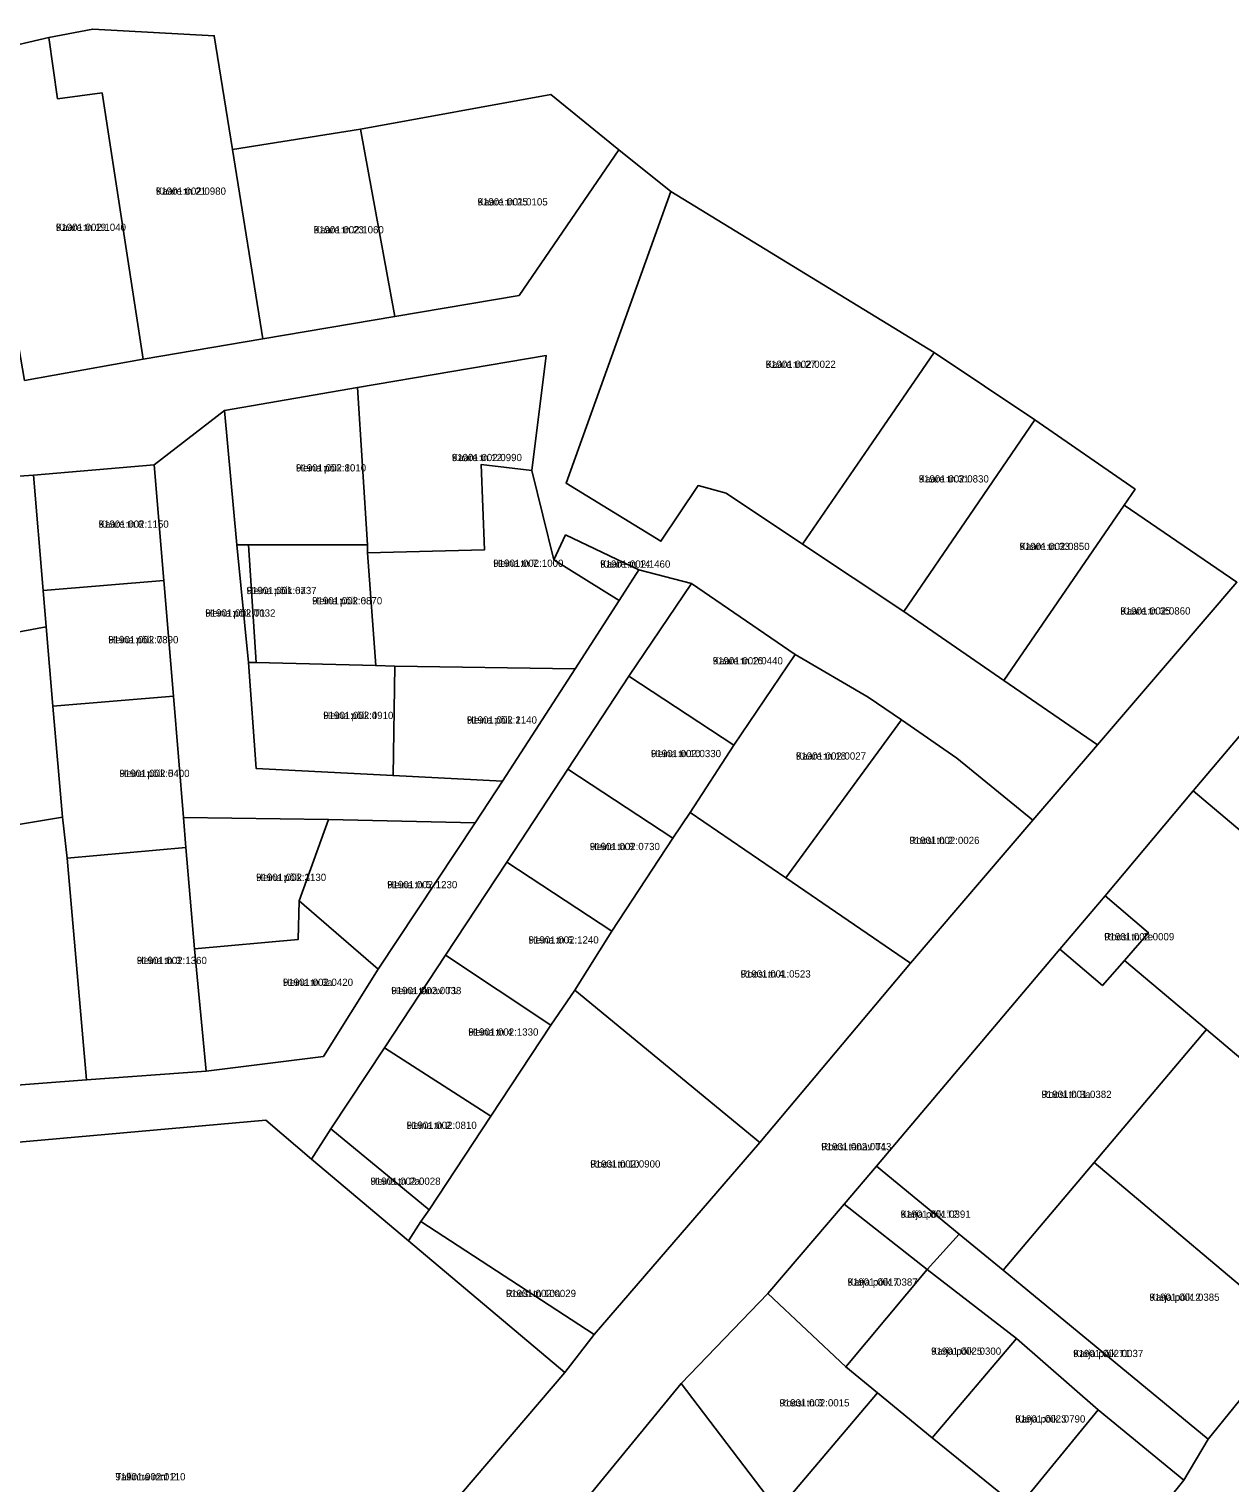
# Model space of a CAD drawing. Extents: x 675810 to 681273, y 6411190 to 6417565.
# Drawn here: x 677544.8 to 677793.2, y 6416055.9 to 6416356.7 of the extents above; entities that cross this region are included whole.
import ezdxf

# ---------------------------------------------------------------- set-up
doc = ezdxf.new("R2010")
doc.units = 0
for name, color, linetype in [('L_AADRESS', 7, 'Continuous'), ('PIIR', 7, 'Continuous'), ('TUNNUS', 7, 'Continuous')]:
    doc.layers.add(name, color=color, linetype=linetype)

msp = doc.modelspace()

# ---------------------------------------------------------------- linework, layer by layer
at = {"layer": 'PIIR'}
for points in [[(677794.67, 6416242.23), (677771.38, 6416258.16), (677773.6, 6416261.47), (677752.89, 6416275.86), (677732.09, 6416289.79), (677677.61, 6416323.04), (677666.82, 6416331.69), (677652.77, 6416343.15), (677613.36, 6416335.95), (677586.93, 6416331.79), (677583.15, 6416355.3), (677558, 6416356.67), (677548.9, 6416354.92), (677532.33, 6416351.09)], [(677543.9, 6416284), (677568.43, 6416288.39), (677593.22, 6416292.61), (677620.49, 6416297.21), (677646.19, 6416301.52), (677666.82, 6416331.69), (677677.61, 6416323.04), (677655.93, 6416262.7), (677675.55, 6416250.7), (677683.22, 6416262.22), (677689.06, 6416260.66), (677704.82, 6416250.12), (677725.81, 6416236.19), (677746.48, 6416221.88), (677765.85, 6416208.59), (677752.5, 6416193.03), (677736.72, 6416205.85), (677725.32, 6416213.74), (677718.38, 6416218.46), (677703.29, 6416227.26), (677681.85, 6416241.97), (677671, 6416244.77), (677655.82, 6416252.03), (677653.38, 6416246.86), (677648.8, 6416265.32), (677651.8, 6416289.14), (677612.76, 6416282.49), (677585.28, 6416277.76), (677570.68, 6416266.51), (677545.77, 6416264.42), (677495.95, 6416260.96)], [(677573.02, 6415981.95), (677655.68, 6416078.76), (677661.7, 6416086.6), (677695.97, 6416126.31), (677727.14, 6416163.4), (677752.5, 6416193.03), (677765.85, 6416208.59), (677781.56, 6416226.93), (677794.67, 6416242.23)], [(677811.12, 6416229.25), (677785.63, 6416199.06), (677767.4, 6416177.34), (677758.08, 6416166.33), (677720.14, 6416121.47), (677713.47, 6416113.6), (677697.68, 6416095.11), (677679.75, 6416076.45), (677660.18, 6416052.71)], [(677794.44, 6416043.2), (677766.1, 6416008.89), (677752.43, 6415991.47), (677738.35, 6415974.82), (677724.5, 6415957.8), (677709.96, 6415939.83), (677697.24, 6415924.42), (677668.6, 6415889.62), (677656.88, 6415902.54), (677667.33, 6415915.23), (677686.11, 6415938), (677714.36, 6415972.29), (677723.5, 6415983.06), (677744.6, 6416008.77), (677762.46, 6416030.29), (677767.35, 6416036.14), (677783.68, 6416056.48), (677788.71, 6416064.93), (677806.76, 6416087.14)]]:
    msp.add_lwpolyline(points, dxfattribs=at)
for points in [[(677568.43, 6416288.39), (677559.92, 6416343.46), (677550.73, 6416342.26), (677548.9, 6416354.92), (677558, 6416356.67), (677583.15, 6416355.3), (677586.93, 6416331.79), (677593.22, 6416292.61)], [(677568.43, 6416288.39), (677543.9, 6416284), (677539.83, 6416307.7), (677532.33, 6416351.09), (677548.9, 6416354.92), (677550.73, 6416342.26), (677559.92, 6416343.46)], [(677620.49, 6416297.21), (677613.36, 6416335.95), (677652.77, 6416343.15), (677666.82, 6416331.69), (677646.19, 6416301.52)], [(677593.22, 6416292.61), (677586.93, 6416331.79), (677613.36, 6416335.95), (677620.49, 6416297.21)], [(677677.61, 6416323.04), (677732.09, 6416289.79), (677718.45, 6416269.95), (677704.82, 6416250.12), (677689.06, 6416260.66), (677683.22, 6416262.22), (677675.55, 6416250.7), (677655.93, 6416262.7)], [(677752.89, 6416275.86), (677739.34, 6416256.01), (677725.81, 6416236.19), (677704.82, 6416250.12), (677718.45, 6416269.95), (677732.09, 6416289.79)], [(677648.8, 6416265.32), (677638.35, 6416266.58), (677639.02, 6416248.93), (677614.86, 6416248.31), (677614.82, 6416249.99), (677612.76, 6416282.49), (677651.8, 6416289.14)], [(677585.28, 6416277.76), (677612.76, 6416282.49), (677614.82, 6416249.99), (677590.22, 6416250), (677587.81, 6416249.99)], [(677585.28, 6416277.76), (677587.81, 6416249.99), (677590.2, 6416225.65), (677591.83, 6416203.68), (677620.14, 6416202.24), (677642.75, 6416201.08), (677637.14, 6416192.47), (677606.8, 6416193.14), (677576.78, 6416193.58), (677574.68, 6416218.68), (677572.68, 6416242.6), (677570.68, 6416266.51)], [(677725.81, 6416236.19), (677739.34, 6416256.01), (677752.89, 6416275.86), (677773.6, 6416261.47), (677771.38, 6416258.16), (677760.06, 6416241.67), (677746.48, 6416221.88)], [(677547.75, 6416240.51), (677545.77, 6416264.42), (677570.68, 6416266.51), (677572.68, 6416242.6)], [(677620.46, 6416224.9), (677616.55, 6416225), (677614.86, 6416248.31), (677639.02, 6416248.93), (677638.35, 6416266.58), (677648.8, 6416265.32), (677653.38, 6416246.86), (677666.87, 6416238.47), (677657.82, 6416224.29)], [(677464.48, 6416246.4), (677495.95, 6416260.96), (677545.77, 6416264.42), (677547.75, 6416240.51), (677548.36, 6416233.03), (677476.27, 6416219.64)], [(677746.48, 6416221.88), (677760.06, 6416241.67), (677771.38, 6416258.16), (677794.67, 6416242.23), (677781.56, 6416226.93), (677765.85, 6416208.59)], [(677671, 6416244.77), (677666.87, 6416238.47), (677653.38, 6416246.86), (677655.82, 6416252.03)], [(677587.81, 6416249.99), (677590.22, 6416250), (677591.82, 6416225.61), (677590.2, 6416225.65)], [(677590.22, 6416250), (677614.82, 6416249.99), (677614.86, 6416248.31), (677616.55, 6416225), (677591.82, 6416225.61)], [(677671, 6416244.77), (677681.85, 6416241.97), (677668.91, 6416222.8), (677656.27, 6416203.57), (677643.64, 6416184.35), (677631, 6416165.12), (677618.37, 6416145.9), (677607.23, 6416129.15), (677603.27, 6416122.92), (677593.8, 6416130.93), (677521.69, 6416124.52), (677474.23, 6416069.26), (677463.05, 6416074.62), (677484.83, 6416099.78), (677508.74, 6416127.38), (677516.04, 6416136.21), (677556.74, 6416139.27), (677581.5, 6416141.12), (677605.73, 6416144.11), (677617.04, 6416162.16), (677637.14, 6416192.47), (677642.75, 6416201.08), (677657.82, 6416224.29), (677666.87, 6416238.47)], [(677549.77, 6416216.59), (677548.38, 6416233.03), (677547.75, 6416240.51), (677572.68, 6416242.6), (677574.68, 6416218.68)], [(677690.64, 6416208.52), (677668.91, 6416222.8), (677681.85, 6416241.97), (677703.29, 6416227.26)], [(677476.27, 6416219.64), (677548.36, 6416233.03), (677549.77, 6416216.59), (677551.75, 6416193.61), (677493.3, 6416183.91)], [(677785.63, 6416199.06), (677811.12, 6416229.25), (677834.51, 6416209.56), (677852.15, 6416194.68), (677826.68, 6416164.44)], [(677703.29, 6416227.26), (677718.38, 6416218.46), (677725.32, 6416213.74), (677701.37, 6416181.06), (677681.6, 6416194.6), (677690.64, 6416208.52)], [(677590.2, 6416225.65), (677591.82, 6416225.61), (677616.55, 6416225), (677620.46, 6416224.9), (677620.14, 6416202.24), (677591.83, 6416203.68)], [(677657.82, 6416224.29), (677642.75, 6416201.08), (677620.14, 6416202.24), (677620.46, 6416224.9)], [(677668.91, 6416222.8), (677690.64, 6416208.52), (677681.6, 6416194.6), (677678, 6416189.3), (677656.27, 6416203.57)], [(677551.75, 6416193.61), (677549.77, 6416216.59), (677574.68, 6416218.68), (677576.78, 6416193.58), (677577.28, 6416187.39), (677552.73, 6416185.15)], [(677725.32, 6416213.74), (677736.72, 6416205.85), (677752.5, 6416193.03), (677727.14, 6416163.4), (677701.37, 6416181.06)], [(677656.27, 6416203.57), (677678, 6416189.3), (677665.37, 6416170.07), (677643.64, 6416184.35)], [(677767.4, 6416177.34), (677785.63, 6416199.06), (677826.68, 6416164.44), (677803.51, 6416136.96), (677788.36, 6416149.72), (677771.41, 6416163.98), (677776.37, 6416169.72)], [(677551.75, 6416193.61), (677552.73, 6416185.15), (677556.74, 6416139.27), (677516.04, 6416136.21), (677493.3, 6416183.91)], [(677577.28, 6416187.39), (677576.78, 6416193.58), (677606.8, 6416193.14), (677600.68, 6416176.34), (677600.49, 6416168.3), (677579.06, 6416166.39)], [(677637.14, 6416192.47), (677617.04, 6416162.16), (677600.68, 6416176.34), (677606.8, 6416193.14)], [(677727.14, 6416163.4), (677695.97, 6416126.31), (677657.71, 6416157.83), (677665.37, 6416170.07), (677678, 6416189.3), (677681.6, 6416194.6), (677701.37, 6416181.06)], [(677577.28, 6416187.39), (677579.06, 6416166.39), (677581.5, 6416141.12), (677556.74, 6416139.27), (677552.73, 6416185.15)], [(677665.37, 6416170.07), (677657.71, 6416157.83), (677652.78, 6416150.64), (677631, 6416165.12), (677643.64, 6416184.35)], [(677600.49, 6416168.3), (677600.68, 6416176.34), (677617.04, 6416162.16), (677605.73, 6416144.11), (677581.5, 6416141.12), (677579.06, 6416166.39)], [(677758.08, 6416166.33), (677767.4, 6416177.34), (677776.37, 6416169.72), (677771.41, 6416163.98), (677766.87, 6416158.78)], [(677720.14, 6416121.47), (677758.08, 6416166.33), (677766.87, 6416158.78), (677771.41, 6416163.98), (677788.36, 6416149.72), (677765.13, 6416122.23), (677746.36, 6416099.92), (677737.24, 6416107.4)], [(677652.78, 6416150.64), (677640.35, 6416131.76), (677618.37, 6416145.9), (677631, 6416165.12)], [(677657.71, 6416157.83), (677695.97, 6416126.31), (677661.7, 6416086.6), (677625.87, 6416109.96), (677627.61, 6416112.4), (677640.35, 6416131.76), (677652.78, 6416150.64)], [(677765.13, 6416122.23), (677788.36, 6416149.72), (677803.51, 6416136.96), (677829.57, 6416114.98), (677812.82, 6416094.62), (677806.76, 6416087.14)], [(677627.61, 6416112.4), (677607.23, 6416129.15), (677618.37, 6416145.9), (677640.35, 6416131.76)], [(677569.88, 6415984.72), (677567.46, 6415999.42), (677560.49, 6416005.51), (677554.29, 6415998.51), (677474.23, 6416069.26), (677521.69, 6416124.52), (677593.8, 6416130.93), (677603.27, 6416122.92), (677623.31, 6416106.01), (677655.68, 6416078.76), (677573.02, 6415981.95)], [(677603.27, 6416122.92), (677607.23, 6416129.15), (677627.61, 6416112.4), (677625.87, 6416109.96), (677623.31, 6416106.01)], [(677713.47, 6416113.6), (677720.14, 6416121.47), (677737.24, 6416107.4), (677730.61, 6416100.05)], [(677746.36, 6416099.92), (677765.13, 6416122.23), (677806.76, 6416087.14), (677788.71, 6416064.93)], [(677697.68, 6416095.11), (677713.47, 6416113.6), (677730.61, 6416100.05), (677713.76, 6416079.92)], [(677625.87, 6416109.96), (677661.7, 6416086.6), (677655.68, 6416078.76), (677623.31, 6416106.01)], [(677737.24, 6416107.4), (677746.36, 6416099.92), (677788.71, 6416064.93), (677783.68, 6416056.48), (677765.98, 6416071.05), (677749.07, 6416085.8), (677730.61, 6416100.05)], [(677730.61, 6416100.05), (677749.07, 6416085.8), (677731.66, 6416065.21), (677720.33, 6416074.55), (677713.76, 6416079.92)], [(677697.68, 6416095.11), (677713.76, 6416079.92), (677720.33, 6416074.55), (677699.71, 6416050.18), (677679.75, 6416076.45)], [(677765.98, 6416071.05), (677749.42, 6416050.8), (677731.66, 6416065.21), (677749.07, 6416085.8)], [(677679.75, 6416076.45), (677699.71, 6416050.18), (677706.01, 6416042.14), (677708.87, 6416038.12), (677706.71, 6416035.65), (677694.76, 6416021.96), (677691.87, 6416024.36), (677660.18, 6416052.71)], [(677720.33, 6416074.55), (677731.66, 6416065.21), (677749.42, 6416050.8), (677767.35, 6416036.14), (677762.46, 6416030.29), (677744.6, 6416008.77), (677729.36, 6416021.81), (677736.58, 6416032.49), (677728.08, 6416040.32), (677720.08, 6416042.3), (677712.05, 6416048.68), (677706.01, 6416042.14), (677699.71, 6416050.18)], [(677765.98, 6416071.05), (677783.68, 6416056.48), (677767.35, 6416036.14), (677749.42, 6416050.8)]]:
    msp.add_lwpolyline(points, close=True, dxfattribs=at)

# ---------------------------------------------------------------- texts
at = {"layer": 'L_AADRESS'}
for s, p in [('Kaare tn 21', (677571.06, 6416322.4)), ('Kaare tn 25', (677637.61, 6416320.18)), ('Kaare tn 19', (677550.38, 6416314.92)), ('Kaare tn 23', (677603.71, 6416314.41)), ('Kaare tn 27', (677697.2, 6416286.58)), ('Kaare tn 12', (677632.28, 6416267.29)), ('Heina põik 8', (677600.05, 6416265.15)), ('Kaare tn 31', (677728.86, 6416262.87)), ('Kaare tn 8', (677559.22, 6416253.51)), ('Kaare tn 33', (677749.71, 6416248.89)), ('Heina tn 7', (677640.86, 6416245.42)), ('Kaare tn 14', (677662.98, 6416245.25)), ('Heina põik 6a', (677589.82, 6416239.78)), ('Heina põik 6', (677603.38, 6416237.66)), ('Heina põik T1', (677581.29, 6416235.12)), ('Kaare tn 35', (677770.57, 6416235.55)), ('Heina põik 7', (677561.22, 6416229.6)), ('Kaare tn 16', (677686.25, 6416225.24)), ('Heina põik 4', (677605.69, 6416213.94)), ('Heina põik 2', (677635.39, 6416212.99)), ('Heina tn 10', (677673.47, 6416206.05)), ('Kaare tn 18', (677703.46, 6416205.54)), ('Heina põik 5', (677563.53, 6416201.94)), ('Heina tn 8', (677660.82, 6416186.82)), ('Roosi tn 2', (677726.93, 6416188.08)), ('Heina põik 3', (677591.79, 6416180.44)), ('Heina tn 5', (677618.91, 6416178.93)), ('Heina tn 6', (677648.16, 6416167.5)), ('Roosi tn 1e', (677767.22, 6416168.16)), ('Heina tn 3', (677567.11, 6416163.25)), ('Heina tn 3a', (677597.35, 6416158.73)), ('Roosi tn 4', (677692.01, 6416160.46)), ('Heina tänav T1', (677619.75, 6416157.02)), ('Heina tn 4', (677635.69, 6416148.44)), ('Roosi tn 3a', (677754.25, 6416135.55)), ('Heina tn 2', (677622.93, 6416129.15)), ('Roosi tänav T1', (677708.7, 6416124.73)), ('Roosi tn 10', (677660.92, 6416121.15)), ('Heina tn 2a', (677615.45, 6416117.58)), ('Karja põik T2', (677725.11, 6416110.76)), ('Karja põik 7', (677714.14, 6416096.72)), ('Roosi tn 10a', (677643.47, 6416094.36)), ('Karja põik 2', (677776.58, 6416093.58)), ('Karja põik 5', (677731.41, 6416082.42)), ('Karja põik T1', (677760.81, 6416081.94)), ('Roosi tn 3', (677700.04, 6416071.73)), ('Karja põik 3', (677748.82, 6416068.4)), ('Tallinna mnt 2', (677562.68, 6416056.44))]:
    msp.add_text(s, height=1.5, dxfattribs=at).set_placement(p)
at = {"layer": 'TUNNUS'}
for s, p in [('91901:002:0980', (677571.06, 6416322.4)), ('91901:001:0105', (677637.61, 6416320.18)), ('91901:002:1040', (677550.38, 6416314.92)), ('91901:002:1060', (677603.71, 6416314.41)), ('91901:002:0022', (677697.2, 6416286.58)), ('91901:002:0990', (677632.28, 6416267.29)), ('91901:002:1010', (677600.05, 6416265.15)), ('91901:002:0830', (677728.86, 6416262.87)), ('91901:002:1150', (677559.22, 6416253.51)), ('91901:002:0850', (677749.71, 6416248.89)), ('91901:002:1000', (677640.86, 6416245.42)), ('91901:002:1460', (677662.98, 6416245.25)), ('91901:001:0737', (677589.82, 6416239.78)), ('91901:002:0870', (677603.38, 6416237.66)), ('91901:002:0032', (677581.29, 6416235.12)), ('91901:002:0860', (677770.57, 6416235.55)), ('91901:002:0890', (677561.22, 6416229.6)), ('91901:002:0440', (677686.25, 6416225.24)), ('91901:002:0910', (677605.69, 6416213.94)), ('91901:002:1140', (677635.39, 6416212.99)), ('91901:002:0330', (677673.47, 6416206.05)), ('91901:002:0027', (677703.46, 6416205.54)), ('91901:002:0400', (677563.53, 6416201.94)), ('91901:002:0730', (677660.82, 6416186.82)), ('91901:002:0026', (677726.93, 6416188.08)), ('91901:002:1130', (677591.79, 6416180.44)), ('91901:002:1230', (677618.91, 6416178.93)), ('91901:002:1240', (677648.16, 6416167.5)), ('91901:002:0009', (677767.22, 6416168.16)), ('91901:002:1360', (677567.11, 6416163.25)), ('91901:002:0420', (677597.35, 6416158.73)), ('91901:001:0523', (677692.01, 6416160.46)), ('91901:002:0038', (677619.75, 6416157.02)), ('91901:002:1330', (677635.69, 6416148.44)), ('91901:001:0382', (677754.25, 6416135.55)), ('91901:002:0810', (677622.93, 6416129.15)), ('91901:002:0043', (677708.7, 6416124.73)), ('91901:002:0900', (677660.92, 6416121.15)), ('91901:002:0028', (677615.45, 6416117.58)), ('91901:001:0391', (677725.11, 6416110.76)), ('91901:001:0387', (677714.14, 6416096.72)), ('91901:002:0029', (677643.47, 6416094.36)), ('91901:001:0385', (677776.58, 6416093.58)), ('91901:002:0300', (677731.41, 6416082.42)), ('91901:002:0037', (677760.81, 6416081.94)), ('91901:002:0015', (677700.04, 6416071.73)), ('91901:002:0790', (677748.82, 6416068.4)), ('91901:002:0110', (677562.68, 6416056.44))]:
    msp.add_text(s, height=1.5, dxfattribs=at).set_placement(p)

doc.saveas('drawing.dxf')
